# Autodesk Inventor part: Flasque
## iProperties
Shininess: 64.0
Length Units: 11269
Angle Units: 11279
Time Units: 11290
Mass Units: 11283
Length Display Precision: 3
Angle Display Precision: 2
Compacted: True
Part Number: Flasque
Document SubType Name: Modeling
Created: 2005-01
Material: Par défaut
Designer: lolo (Laurent Moretti)
Density: 0.0
Volumn: 0.0
Area: 0.0
PropertySet Name: Model Information
Control State: 0
Master: False
Checked Out: False
Author: lolo (Laurent Moretti)
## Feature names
1. Révolution1 [Revolution]
2. Congé1 [Fillet]
3. Congé2 [Fillet]
4. Chanfrein1 [Chamfer]
5. Chanfrein2 [Chamfer]
6. Extrusion1
7. Extrusion2
8. Congé3 [Fillet]
9. Réseau circulaire1 [Circular Pattern]
10. Perçage1 [Hole]
11. Extrusion3
12. Réseau circulaire2 [Circular Pattern]
13. Perçage2 [Hole]
14. Réseau circulaire3 [Circular Pattern]
15. Extrusion4
16. Perçage3 [Hole]
17. Symétrie1 [Mirror]
18. Symétrie2 [Mirror]
